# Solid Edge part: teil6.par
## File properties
Author: Susi
Template: Normal.par
Last saved by: Susi
Revision: 1
Application: Solid Edge
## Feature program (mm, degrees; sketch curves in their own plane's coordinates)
sketch for "unnamed Protrusion 1" plane through (0, 0, 0) normal (0, 0, 1) x-axis (1, 0, 0)
extrude "unnamed Protrusion 1" add finite 10 along +normal
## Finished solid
Body 1: solid body, 6 faces, 12 edges, 8 vertices.
  Faces by surface: plane 6
  Edges by curve: line 12
Bounding box of the edges (mm): 2.000 x 15.000 x 10.000, from (-24.5333, -27.2, 0) to (-22.5333, -12.2, 10).
Planar faces by outward normal: +x 1, +y 1, +z 1, -x 1, -y 1, -z 1
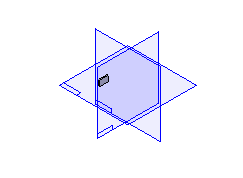
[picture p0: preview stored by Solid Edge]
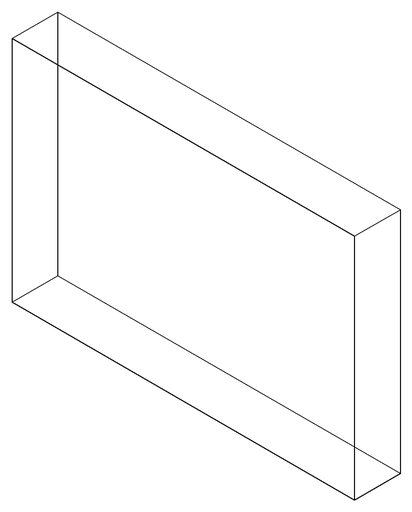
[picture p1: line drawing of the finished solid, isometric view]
